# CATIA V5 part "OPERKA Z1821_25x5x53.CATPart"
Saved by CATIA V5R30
Part number: OPERKA VETSI
Bounding box of the stored display mesh (mm): x -9.767 to 4.289, y -12.216 to 11.784, z -26.5 to 26.5
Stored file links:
  C:\Users\ondra\Desktop\PŘÍLOHA P III\CATIA\OPERKA Z1821_25x5x53.CATPart
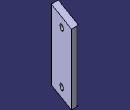
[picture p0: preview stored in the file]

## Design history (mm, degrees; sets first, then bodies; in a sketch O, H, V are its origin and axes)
Set1
  DatumSurface1 to DatumSurface19 "Z1821/25"
  Plane1: type Tangent, Support DatumSurface15, RefPoint vertex [face of DatumSurface18]
  Plane2: type Tangent, Support DatumSurface14, RefPoint vertex [face of DatumSurface18]
  Plane3: type Tangent, Support DatumSurface18, RefPoint vertex [face of DatumSurface15]
  Plane4: type Tangent, Support DatumSurface17, RefPoint vertex [face of DatumSurface16]
  Point1: type OnSurface, Support DatumSurface17, Length 0, Direction edge of DatumSurface8
  Plane5: type Tangent, Support DatumSurface17, RefPoint Point1
  Join1: Elements (DatumSurface1; DatumSurface2; DatumSurface3; DatumSurface4; DatumSurface5; DatumSurface6; DatumSurface7; DatumSurface8; DatumSurface9; DatumSurface10; DatumSurface11; DatumSurface12; DatumSurface13; DatumSurface14; DatumSurface15; DatumSurface16; DatumSurface17; DatumSurface18; DatumSurface19)
Body1 (main body)
  CloseSurface1: CloseElement Join1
